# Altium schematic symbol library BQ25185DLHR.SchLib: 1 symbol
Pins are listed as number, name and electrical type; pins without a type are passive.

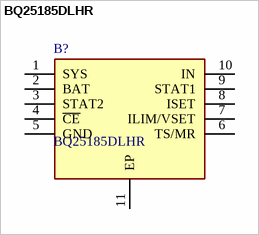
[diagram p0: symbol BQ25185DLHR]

## BQ25185DLHR
designator B?
Battery Management NPI  1-CELL 1A STANDALONE LNR HRGR; Manufacturer_Name: Texas Instruments; Geometry.Height: 0.8mm
footprint SON40P220X200X80-11N
pins: 1 SYS, 2 BAT, 3 STAT2, 4 ~{CE}, 5 GND, 6 TS/MR, 7 ILIM/VSET, 8 ISET, 9 STAT1, 10 IN, 11 EP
